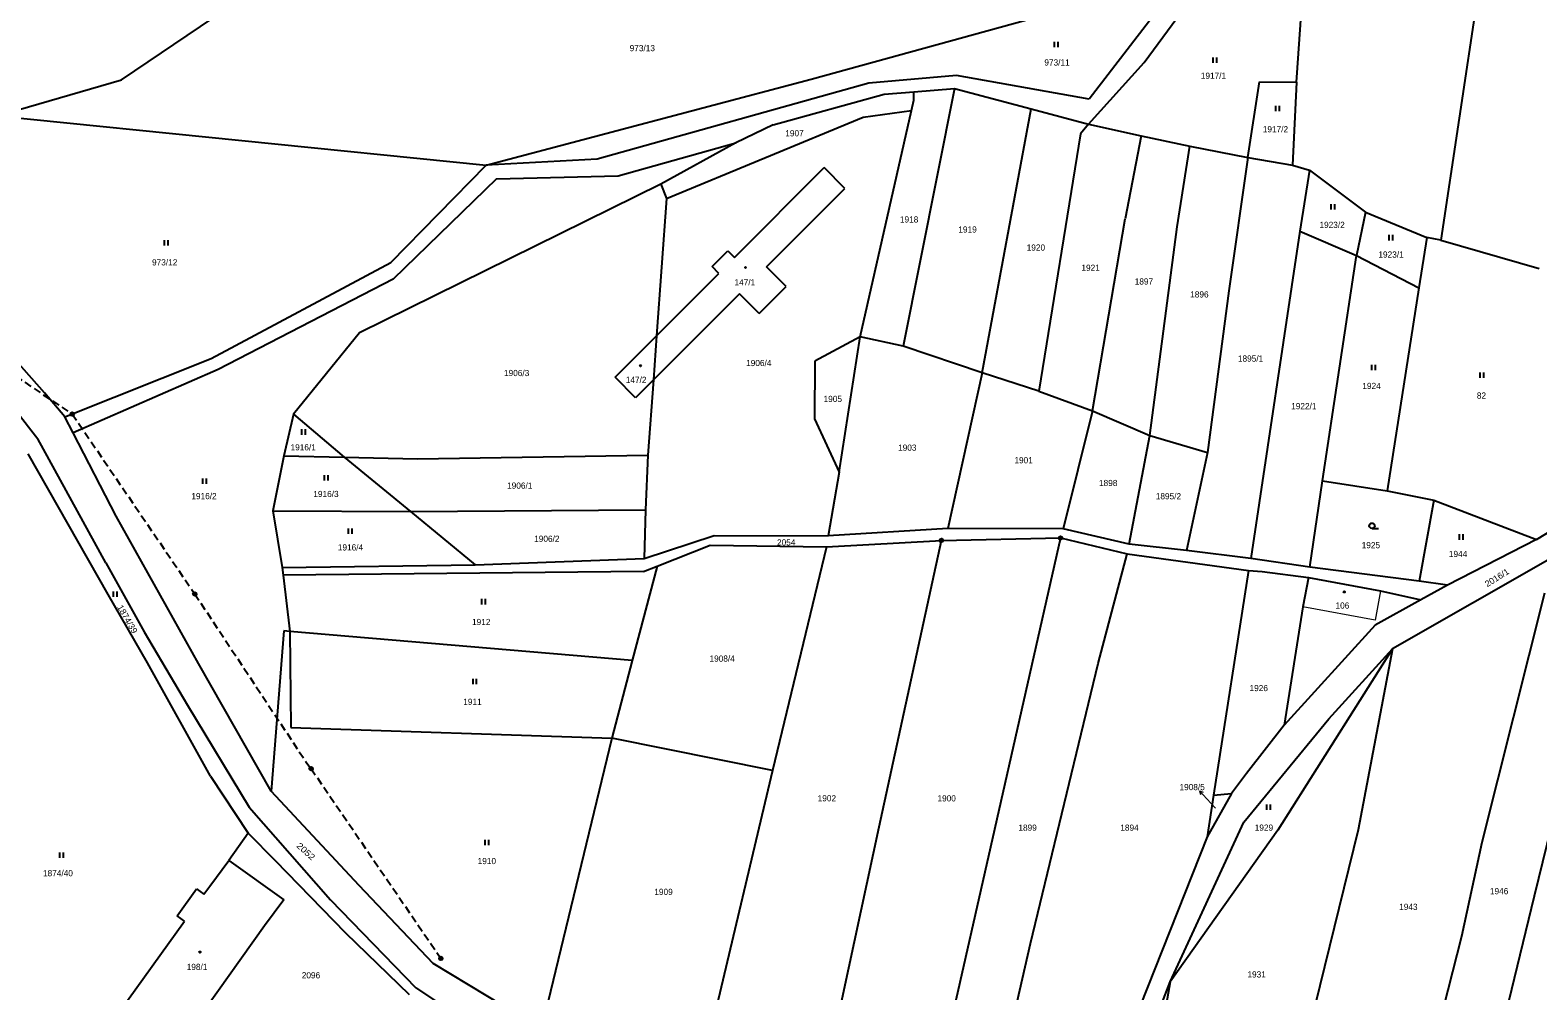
# Model space of a CAD drawing. Extents: x -820420 to -815896, y -1105820 to -1103643.
# Drawn here: x -818234.8 to -817820.3, y -1105183.5 to -1104919.6 of the extents above; entities that cross this region are included whole.
import ezdxf
from ezdxf.enums import TextEntityAlignment as Align

# ---------------------------------------------------------------- set-up
doc = ezdxf.new("R2010")
doc.units = 0
doc.header["$LTSCALE"] = 0.68
doc.linetypes.add('MEDIUM_DASHED', pattern=[4.5, 3, -1.5])
for name, color, linetype, lineweight in [('1', 7, 'Continuous', 25), ('3', 7, 'Continuous', 25), ('4', 7, 'Continuous', 13), ('5', 7, 'Continuous', 25), ('6', 7, 'Continuous', 25), ('7', 7, 'Continuous', 13), ('8', 7, 'Continuous', 25)]:
    doc.layers.add(name, color=color, linetype=linetype, lineweight=lineweight)
doc.layers.add('2', color=7, linetype='Continuous')

msp = doc.modelspace()

# ---------------------------------------------------------------- linework, layer by layer
at = {"layer": '1'}
for p, q in [((-817886.64, -1104933.91), (-817884.23, -1104898.39)), ((-818020.08, -1104933.05), (-817930.9, -1104908.48)), ((-817920.67, -1104908.63), (-817943.64, -1104938.51)), ((-817836.56, -1104907.89), (-817847.04, -1104977.28)), ((-817928.58, -1104928.45), (-817915.74, -1104911)), ((-818209.66, -1104933.2), (-818184.22, -1104916.07)), ((-817943.87, -1104945.43), (-817928.58, -1104928.45)), ((-818243.82, -1104943.13), (-818209.66, -1104933.2)), ((-818109.44, -1104956.69), (-818020.08, -1104933.05)), ((-818004.24, -1104934.14), (-818078.89, -1104955.06)), ((-817980.08, -1104932.04), (-818004.24, -1104934.14)), ((-817943.64, -1104938.51), (-817980.08, -1104932.04)), ((-817900.05, -1104954.58), (-817896.82, -1104933.8)), ((-817896.82, -1104933.8), (-817886.64, -1104933.91)), ((-817886.64, -1104933.91), (-817887.81, -1104956.65)), ((-818030.5, -1104945.58), (-818000.02, -1104937.21)), ((-818000.02, -1104937.21), (-817991.86, -1104936.53)), ((-817980.63, -1104935.6), (-817994.8, -1105006.42)), ((-817992.53, -1104941.61), (-817991.86, -1104938.77)), ((-817991.86, -1104936.53), (-817980.63, -1104935.6)), ((-817991.86, -1104938.77), (-817991.86, -1104936.53)), ((-817980.63, -1104935.6), (-817959.6, -1104941.16)), ((-818243.82, -1104943.13), (-818109.44, -1104956.69)), ((-818006.61, -1105003.81), (-817992.53, -1104941.61)), ((-818005.78, -1104943.53), (-817992.53, -1104941.61)), ((-817959.6, -1104941.16), (-817943.87, -1104945.43)), ((-818059.83, -1104965.81), (-818005.78, -1104943.53)), ((-818030.5, -1104945.58), (-818040.77, -1104950.5)), ((-817943.87, -1104945.43), (-817946, -1104948.08)), ((-817943.87, -1104945.43), (-817929.39, -1104948.57)), ((-818073.09, -1104959.62), (-818040.77, -1104950.5)), ((-818040.77, -1104950.5), (-818061.35, -1104961.9)), ((-817946, -1104948.08), (-817957.51, -1105018.81)), ((-817929.39, -1104948.57), (-817933.79, -1104971.4)), ((-817929.39, -1104948.57), (-817915.96, -1104951.48)), ((-818078.89, -1104955.06), (-818109.44, -1104956.69)), ((-817919.5, -1104973.6), (-817915.96, -1104951.48)), ((-817915.96, -1104951.48), (-817900.05, -1104954.58)), ((-817900.05, -1104954.58), (-817905.24, -1104991.22)), ((-817900.05, -1104954.58), (-817887.81, -1104956.65)), ((-818135.64, -1104983.38), (-818109.44, -1104956.69)), ((-818106.61, -1104960.44), (-818073.09, -1104959.62)), ((-818041.11, -1104982.05), (-818016.48, -1104957.36)), ((-818010.78, -1104963.07), (-818016.48, -1104957.36)), ((-817887.81, -1104956.65), (-817883.1, -1104958.06)), ((-817883.1, -1104958.06), (-817885.77, -1104974.81)), ((-817883.1, -1104958.06), (-817867.68, -1104969.59)), ((-818061.35, -1104961.9), (-818144.18, -1105002.78)), ((-818106.61, -1104960.44), (-818134.93, -1104987.98)), ((-818061.35, -1104961.9), (-818059.83, -1104965.81)), ((-818032.39, -1104984.64), (-818010.78, -1104963.07)), ((-818059.83, -1104965.81), (-818062.56, -1105003.56)), ((-817942.7, -1105024.16), (-817933.79, -1104971.4)), ((-817867.68, -1104969.59), (-817870.14, -1104981.51)), ((-817867.68, -1104969.59), (-817850.86, -1104976.54)), ((-817926.99, -1105030.93), (-817919.5, -1104973.6)), ((-817885.77, -1104974.81), (-817899.26, -1105064.73)), ((-817885.77, -1104974.81), (-817870.14, -1104981.51)), ((-818047.28, -1104984.56), (-818042.95, -1104980.22)), ((-818042.95, -1104980.22), (-818041.11, -1104982.05)), ((-817850.86, -1104976.54), (-817853.01, -1104990.35)), ((-817847.04, -1104977.28), (-817850.86, -1104976.54)), ((-817847.04, -1104977.28), (-817819.95, -1104985.04)), ((-818184.99, -1105009.81), (-818135.64, -1104983.38)), ((-818045.44, -1104986.4), (-818047.28, -1104984.56)), ((-817879.56, -1105043.38), (-817870.14, -1104981.51)), ((-817870.14, -1104981.51), (-817853.01, -1104990.35)), ((-818134.93, -1104987.98), (-818183.09, -1105012.82)), ((-818062.56, -1105003.56), (-818045.44, -1104986.4)), ((-818026.97, -1104990.05), (-818032.39, -1104984.64)), ((-818039.79, -1104992.06), (-818063.44, -1105015.68)), ((-818034.37, -1104997.47), (-818039.79, -1104992.06)), ((-818034.37, -1104997.47), (-818026.97, -1104990.05)), ((-817905.24, -1104991.22), (-817911.11, -1105035.61)), ((-817853.01, -1104990.35), (-817861.79, -1105046.19)), ((-818230.78, -1105019.24), (-818247.51, -1105000.38)), ((-818144.18, -1105002.78), (-818162.35, -1105025.05)), ((-818073.92, -1105014.95), (-818062.56, -1105003.56)), ((-818062.56, -1105003.56), (-818063.44, -1105015.68)), ((-818006.61, -1105003.81), (-818019.03, -1105010.51)), ((-818012.37, -1105040.99), (-818006.61, -1105003.81)), ((-817994.8, -1105006.42), (-818006.61, -1105003.81)), ((-818253.02, -1105005.75), (-818232.64, -1105031.91)), ((-817973.09, -1105013.72), (-817994.8, -1105006.42)), ((-818225.19, -1105025.85), (-818184.99, -1105009.81)), ((-818183.09, -1105012.82), (-818222.95, -1105030.18)), ((-818019.03, -1105010.51), (-818019.14, -1105026.35)), ((-818068.35, -1105020.59), (-818073.92, -1105014.95)), ((-818063.44, -1105015.68), (-818068.35, -1105020.59)), ((-818063.44, -1105015.68), (-818064.93, -1105036.37)), ((-817973.09, -1105013.72), (-817982.55, -1105056.55)), ((-818225.19, -1105025.85), (-818230.78, -1105019.24)), ((-817957.51, -1105018.81), (-817942.7, -1105024.16)), ((-818222.95, -1105030.18), (-818225.19, -1105025.85)), ((-818162.35, -1105025.05), (-818165, -1105036.5)), ((-818162.35, -1105025.05), (-818148.44, -1105036.88)), ((-817942.7, -1105024.16), (-817950.77, -1105056.57)), ((-817942.7, -1105024.16), (-817926.99, -1105030.93)), ((-818211.14, -1105053.1), (-818222.95, -1105030.18)), ((-818019.14, -1105026.35), (-818012.37, -1105040.99)), ((-818213.98, -1105065.96), (-818232.64, -1105031.91)), ((-817932.64, -1105060.77), (-817926.99, -1105030.93)), ((-817926.99, -1105030.93), (-817911.11, -1105035.61)), ((-818213.33, -1105074.62), (-818235.27, -1105035.96)), ((-818165, -1105036.5), (-818168.04, -1105051.62)), ((-818165, -1105036.5), (-818148.44, -1105036.88)), ((-818148.44, -1105036.88), (-818128.27, -1105037.35)), ((-818148.44, -1105036.88), (-818130.22, -1105051.87)), ((-818128.27, -1105037.35), (-818064.93, -1105036.37)), ((-818064.93, -1105036.37), (-818065.58, -1105051.36)), ((-817911.11, -1105035.61), (-817916.88, -1105062.58)), ((-818012.37, -1105040.99), (-818015.42, -1105058.57)), ((-817882.99, -1105067.11), (-817879.56, -1105043.38)), ((-817879.56, -1105043.38), (-817861.79, -1105046.19)), ((-817861.79, -1105046.19), (-817848.91, -1105048.7)), ((-817848.91, -1105048.7), (-817852.92, -1105071)), ((-817848.91, -1105048.7), (-817820.71, -1105059.52)), ((-817820.71, -1105059.52), (-817804.95, -1105049.87)), ((-818188.45, -1105093.62), (-818211.14, -1105053.1)), ((-818168.04, -1105051.62), (-818165.5, -1105067.21)), ((-818168.04, -1105051.62), (-818130.22, -1105051.87)), ((-818130.22, -1105051.87), (-818065.58, -1105051.36)), ((-818130.22, -1105051.87), (-818112.4, -1105066.49)), ((-818065.58, -1105051.36), (-818065.97, -1105064.79)), ((-818065.97, -1105064.79), (-818046.77, -1105058.39)), ((-818046.77, -1105058.39), (-818015.42, -1105058.57)), ((-817982.55, -1105056.55), (-818015.42, -1105058.57)), ((-817984.29, -1105059.79), (-817951.55, -1105059.12)), ((-817950.77, -1105056.57), (-817982.55, -1105056.55)), ((-817951.55, -1105059.12), (-817970.82, -1105144.11)), ((-817951.55, -1105059.12), (-817933.19, -1105063.51)), ((-817932.64, -1105060.77), (-817950.77, -1105056.57)), ((-818062.38, -1105066.83), (-818047.83, -1105061.05)), ((-818047.83, -1105061.05), (-818015.85, -1105061.52)), ((-818015.85, -1105061.52), (-818030.7, -1105123.01)), ((-818015.85, -1105061.52), (-817984.29, -1105059.79)), ((-818001.39, -1105138.46), (-817984.29, -1105059.79)), ((-817916.88, -1105062.58), (-817932.64, -1105060.77)), ((-817899.26, -1105064.73), (-817916.88, -1105062.58)), ((-817820.71, -1105059.52), (-817845.12, -1105072.06)), ((-818213.98, -1105065.96), (-818203.43, -1105084.93)), ((-818165.5, -1105067.21), (-818112.4, -1105066.49)), ((-818165.5, -1105067.21), (-818165.24, -1105069.33)), ((-818112.4, -1105066.49), (-818065.97, -1105064.79)), ((-818062.38, -1105066.83), (-818069.23, -1105092.75)), ((-818066.19, -1105068.35), (-818062.38, -1105066.83)), ((-817941.18, -1105093.57), (-817933.19, -1105063.51)), ((-817933.19, -1105063.51), (-817899.88, -1105068.02)), ((-817882.99, -1105067.11), (-817899.26, -1105064.73)), ((-817852.92, -1105071), (-817882.99, -1105067.11)), ((-817816.27, -1105064.48), (-817860.24, -1105089.62)), ((-818066.19, -1105068.35), (-818165.24, -1105069.33)), ((-818165.24, -1105069.33), (-818163.38, -1105084.82)), ((-817899.88, -1105068.02), (-817909.44, -1105129.8)), ((-817899.88, -1105068.02), (-817896.14, -1105068.37)), ((-817896.14, -1105068.37), (-817883.4, -1105069.96)), ((-817883.4, -1105069.96), (-817884.89, -1105078.03)), ((-817883.4, -1105069.96), (-817863.54, -1105073.62)), ((-817845.12, -1105072.06), (-817852.92, -1105071)), ((-818202.54, -1105093.44), (-818213.33, -1105074.62)), ((-817863.54, -1105073.62), (-817852.47, -1105076.14)), ((-817845.12, -1105072.06), (-817852.47, -1105076.14)), ((-817835.64, -1105142.66), (-817818.39, -1105074.2)), ((-817884.89, -1105078.03), (-817890.05, -1105110.58)), ((-817852.47, -1105076.14), (-817865.02, -1105083.11)), ((-817865.02, -1105083.11), (-817890.05, -1105110.58)), ((-818203.43, -1105084.93), (-818191.54, -1105105.06)), ((-818164.99, -1105084.62), (-818168.47, -1105128.65)), ((-818163.38, -1105084.82), (-818164.99, -1105084.62)), ((-818163.38, -1105084.82), (-818163.12, -1105111.18)), ((-818069.23, -1105092.75), (-818163.38, -1105084.82)), ((-817803.95, -1105086.25), (-817821.32, -1105157.54)), ((-817860.24, -1105089.62), (-817891.78, -1105139.41)), ((-817877.8, -1105108.85), (-817860.24, -1105089.62)), ((-817860.24, -1105089.62), (-817869.71, -1105139.34)), ((-818185.14, -1105124.55), (-818202.54, -1105093.44)), ((-818168.47, -1105128.65), (-818188.45, -1105093.62)), ((-818069.23, -1105092.75), (-818074.84, -1105114.15)), ((-817959.81, -1105170.56), (-817941.18, -1105093.57)), ((-818191.54, -1105105.06), (-818174.55, -1105133.11)), ((-817901.12, -1105137.24), (-817877.8, -1105108.85)), ((-818163.12, -1105111.18), (-818074.84, -1105114.15)), ((-817890.05, -1105110.58), (-817900.42, -1105123.84)), ((-818074.84, -1105114.15), (-818093.85, -1105192.47)), ((-818030.7, -1105123.01), (-818074.84, -1105114.15)), ((-818185.14, -1105124.55), (-818174.87, -1105140.21)), ((-818030.7, -1105123.01), (-818050.33, -1105205.94)), ((-817900.42, -1105123.84), (-817904.53, -1105129.37)), ((-818144.32, -1105154.6), (-818168.47, -1105128.65)), ((-817904.53, -1105129.37), (-817911.24, -1105141.23)), ((-817909.44, -1105129.8), (-817904.53, -1105129.37)), ((-818174.55, -1105133.11), (-818152.22, -1105158.54)), ((-817909.44, -1105129.8), (-817911.24, -1105141.23)), ((-817921.42, -1105181.08), (-817901.12, -1105137.24)), ((-818174.87, -1105140.21), (-818180.11, -1105147.7)), ((-818174.87, -1105140.21), (-818167.4, -1105147.72)), ((-818018.26, -1105216.82), (-818001.39, -1105138.46)), ((-817911.24, -1105141.23), (-817945.61, -1105227.86)), ((-817891.78, -1105139.41), (-817921.42, -1105181.08)), ((-817869.71, -1105139.34), (-817893.45, -1105235.53)), ((-817970.82, -1105144.11), (-817990.04, -1105228.74)), ((-817841.26, -1105168.5), (-817835.64, -1105142.66)), ((-818185.4, -1105154.81), (-818180.11, -1105147.7)), ((-818180.11, -1105147.7), (-818165.05, -1105158.52)), ((-818167.4, -1105147.72), (-818148.06, -1105167.57)), ((-818194.36, -1105162.94), (-818189, -1105155.51)), ((-818189, -1105155.51), (-818186.97, -1105156.98)), ((-818186.97, -1105156.98), (-818185.4, -1105154.81)), ((-818165.05, -1105158.52), (-818170.31, -1105165.69)), ((-818152.22, -1105158.54), (-818128.75, -1105182.72)), ((-818123.98, -1105176.08), (-818144.32, -1105154.6)), ((-817821.32, -1105157.54), (-817842.63, -1105244.78)), ((-818212.24, -1105192.03), (-818192.32, -1105164.41)), ((-818192.32, -1105164.41), (-818194.36, -1105162.94)), ((-818170.31, -1105165.69), (-818193.33, -1105197.91)), ((-818148.06, -1105167.57), (-818130.53, -1105184.58)), ((-817973.59, -1105231.41), (-817959.81, -1105170.56)), ((-817858.96, -1105238.36), (-817841.26, -1105168.5)), ((-818099.7, -1105190.68), (-818123.98, -1105176.08)), ((-818128.75, -1105182.72), (-818119.23, -1105189.07)), ((-817944.12, -1105240.74), (-817921.42, -1105181.08)), ((-817921.42, -1105181.08), (-817929.76, -1105229.05))]:
    msp.add_line(p, q, dxfattribs=at)
msp.add_lwpolyline([(-817957.51, -1105018.81), (-817973.09, -1105013.72), (-817959.6, -1104941.16)], dxfattribs=at)
at = {"layer": '3'}
for p, q in [((-817953.181, -1104924.25), (-817953.181, -1104922.75)), ((-817952.18, -1104924.25), (-817952.18, -1104922.75)), ((-817909.601, -1104928.56), (-817909.601, -1104927.06)), ((-817908.6, -1104928.56), (-817908.6, -1104927.06)), ((-817892.381, -1104941.88), (-817892.381, -1104940.38)), ((-817891.38, -1104941.88), (-817891.38, -1104940.38)), ((-817877.171, -1104968.87), (-817877.171, -1104967.37)), ((-817876.17, -1104968.87), (-817876.17, -1104967.37)), ((-817861.231, -1104977.36), (-817861.231, -1104975.86)), ((-817860.23, -1104977.36), (-817860.23, -1104975.86)), ((-818197.861, -1104978.75), (-818197.861, -1104977.25)), ((-818196.86, -1104978.75), (-818196.86, -1104977.25)), ((-817865.961, -1105013.01), (-817865.961, -1105011.51)), ((-817864.96, -1105013.01), (-817864.96, -1105011.51)), ((-817836.191, -1105015.1), (-817836.191, -1105013.6)), ((-817835.19, -1105015.1), (-817835.19, -1105013.6)), ((-818160.081, -1105030.74), (-818160.081, -1105029.24)), ((-818159.08, -1105030.74), (-818159.08, -1105029.24)), ((-818153.851, -1105043.33), (-818153.851, -1105041.83)), ((-818152.85, -1105043.33), (-818152.85, -1105041.83)), ((-818187.241, -1105044.24), (-818187.241, -1105042.74)), ((-818186.24, -1105044.24), (-818186.24, -1105042.74)), ((-818147.211, -1105058.02), (-818147.211, -1105056.52)), ((-818146.21, -1105058.02), (-818146.21, -1105056.52)), ((-817865.913, -1105056.5), (-817864.163, -1105056.5)), ((-817841.901, -1105059.6), (-817841.901, -1105058.1)), ((-817840.9, -1105059.6), (-817840.9, -1105058.1)), ((-818211.831, -1105075.33), (-818211.831, -1105073.83)), ((-818210.83, -1105075.33), (-818210.83, -1105073.83)), ((-818110.611, -1105077.36), (-818110.611, -1105075.86)), ((-818109.61, -1105077.36), (-818109.61, -1105075.86)), ((-818113.021, -1105099.29), (-818113.021, -1105097.79)), ((-818112.02, -1105099.29), (-818112.02, -1105097.79)), ((-817894.811, -1105133.82), (-817894.811, -1105132.32)), ((-817893.81, -1105133.82), (-817893.81, -1105132.32)), ((-818109.711, -1105143.54), (-818109.711, -1105142.04)), ((-818108.71, -1105143.54), (-818108.71, -1105142.04)), ((-818226.551, -1105147.02), (-818226.551, -1105145.52)), ((-818225.55, -1105147.02), (-818225.55, -1105145.52))]:
    msp.add_line(p, q, dxfattribs=at)
msp.add_circle((-817865.9129, -1105055.7498), 0.75, dxfattribs=at)
at = {"layer": '4'}
for p, q in [((-817863.54, -1105073.62), (-817865.04, -1105081.73)), ((-817865.04, -1105081.73), (-817884.89, -1105078.03))]:
    msp.add_line(p, q, dxfattribs=at)
at = {"layer": '5'}
for centre in [(-818038.1168, -1104984.7992), (-818066.9868, -1105011.7892), (-817873.5368, -1105073.9392), (-818188.0768, -1105172.8992)]:
    msp.add_circle(centre, 0.175, dxfattribs=at)
at = {"layer": '6', "linetype": 'MEDIUM_DASHED'}
for p, q in [((-818294.69, -1104977.15), (-818223.17, -1105025.08)), ((-818223.17, -1105025.08), (-818189.51, -1105074.51)), ((-818189.51, -1105074.51), (-818158.69, -1105121)), ((-818158.69, -1105121), (-818157.52, -1105122.51)), ((-818157.52, -1105122.51), (-818121.86, -1105174.64))]:
    msp.add_line(p, q, dxfattribs=at)
at = {"layer": '6'}
for centre, radius in [((-818223.1734, -1105025.0799), 0.5), ((-818223.1734, -1105025.0799), 0.4), ((-818223.1734, -1105025.0799), 0.3), ((-818223.1734, -1105025.0799), 0.2), ((-818223.1734, -1105025.0799), 0.1), ((-818189.5134, -1105074.5099), 0.5), ((-818189.5134, -1105074.5099), 0.4), ((-818189.5134, -1105074.5099), 0.3), ((-818189.5134, -1105074.5099), 0.2), ((-818189.5134, -1105074.5099), 0.1), ((-818157.5234, -1105122.5099), 0.5), ((-818157.5234, -1105122.5099), 0.4), ((-818157.5234, -1105122.5099), 0.3), ((-818157.5234, -1105122.5099), 0.2), ((-818157.5234, -1105122.5099), 0.1), ((-818121.8634, -1105174.6399), 0.5), ((-818121.8634, -1105174.6399), 0.4), ((-818121.8634, -1105174.6399), 0.3), ((-818121.8634, -1105174.6399), 0.2), ((-818121.8634, -1105174.6399), 0.1)]:
    msp.add_circle(centre, radius, dxfattribs=at)
at = {"layer": '7'}
msp.add_line((-817913.328, -1105128.56), (-817913.03, -1105129.639), dxfattribs=at)
msp.add_lwpolyline([(-817908.94, -1105133.39), (-817911.32, -1105130.79), (-817913.328, -1105128.56), (-817912.286, -1105128.969)], dxfattribs=at)
at = {"layer": '8'}
for centre, radius in [((-817951.55, -1105059.1199), 0.5), ((-817951.55, -1105059.1199), 0.0303), ((-817984.29, -1105059.7899), 0.5), ((-817984.29, -1105059.7899), 0.0303)]:
    msp.add_circle(centre, radius, dxfattribs=at)

# ---------------------------------------------------------------- texts
at = {"layer": '2'}
for s, p in [('973/13', (-818066.49, -1104925.355)), ('973/11', (-817952.5, -1104929.305)), ('1917/1', (-817909.49, -1104932.945)), ('1907', (-818024.66, -1104948.755)), ('1917/2', (-817892.46, -1104947.655)), ('1918', (-817993.15, -1104972.435)), ('1923/2', (-817876.88, -1104973.935)), ('1919', (-817977.09, -1104975.195)), ('1920', (-817958.3, -1104980.165)), ('1923/1', (-817860.68, -1104982.085)), ('973/12', (-818197.77, -1104984.225)), ('1921', (-817943.26, -1104985.705)), ('147/1', (-818038.3, -1104989.715)), ('1897', (-817928.61, -1104989.475)), ('1896', (-817913.36, -1104993.035)), ('1895/1', (-817899.3, -1105010.665)), ('1906/3', (-818101.03, -1105014.635)), ('1906/4', (-818034.47, -1105011.885)), ('147/2', (-818068.19, -1105016.515)), ('1924', (-817866.04, -1105018.185)), ('1905', (-818014.13, -1105021.755)), ('82', (-817835.829, -1105020.835)), ('1922/1', (-817884.65, -1105023.735)), ('1916/1', (-818159.7, -1105035.055)), ('1903', (-817993.65, -1105035.145)), ('1901', (-817961.67, -1105038.595)), ('1916/2', (-818186.96, -1105048.455)), ('1916/3', (-818153.44, -1105047.875)), ('1906/1', (-818100.17, -1105045.575)), ('1898', (-817938.43, -1105044.855)), ('1895/2', (-817921.87, -1105048.495)), ('1906/2', (-818092.73, -1105060.185)), ('1916/4', (-818146.7, -1105062.555)), ('2054', (-818026.93, -1105061.175)), ('1925', (-817866.22, -1105061.935)), ('1944', (-817842.26, -1105064.355)), ('106', (-817874.049, -1105078.525)), ('1912', (-818110.76, -1105083.045)), ('1908/4', (-818044.54, -1105093.105)), ('1926', (-817897.05, -1105101.205)), ('1911', (-818113.17, -1105104.975)), ('1902', (-818015.76, -1105131.485)), ('1900', (-817982.83, -1105131.505)), ('1899', (-817960.58, -1105139.565)), ('1894', (-817932.57, -1105139.565)), ('1929', (-817895.62, -1105139.555)), ('1874/40', (-818227.109, -1105152.065)), ('1910', (-818109.22, -1105148.735)), ('1909', (-818060.65, -1105157.205)), ('1946', (-817830.98, -1105157.005)), ('1943', (-817855.92, -1105161.325)), ('198/1', (-818188.87, -1105177.825)), ('2096', (-818157.56, -1105180.115)), ('1931', (-817897.63, -1105179.885))]:
    msp.add_text(s, height=1.7, dxfattribs=at).set_placement(p, align=Align.CENTER)
for s, rotation, width, p in [('2016/1', 32, 1.05, (-817831.1249, -1105070.7367)), ('1874/39', 300, 1.05, (-818208.7529, -1105081.838)), ('2052', 318, 1.15, (-818159.5248, -1105145.8658))]:
    msp.add_text(s, height=1.7, rotation=rotation, dxfattribs=dict(at, width=width)).set_placement(p, align=Align.CENTER)
msp.add_text('1908/5', height=1.7, dxfattribs=at).set_placement((-817911.879, -1105128.415), align=Align.RIGHT)

doc.saveas('drawing.dxf')
